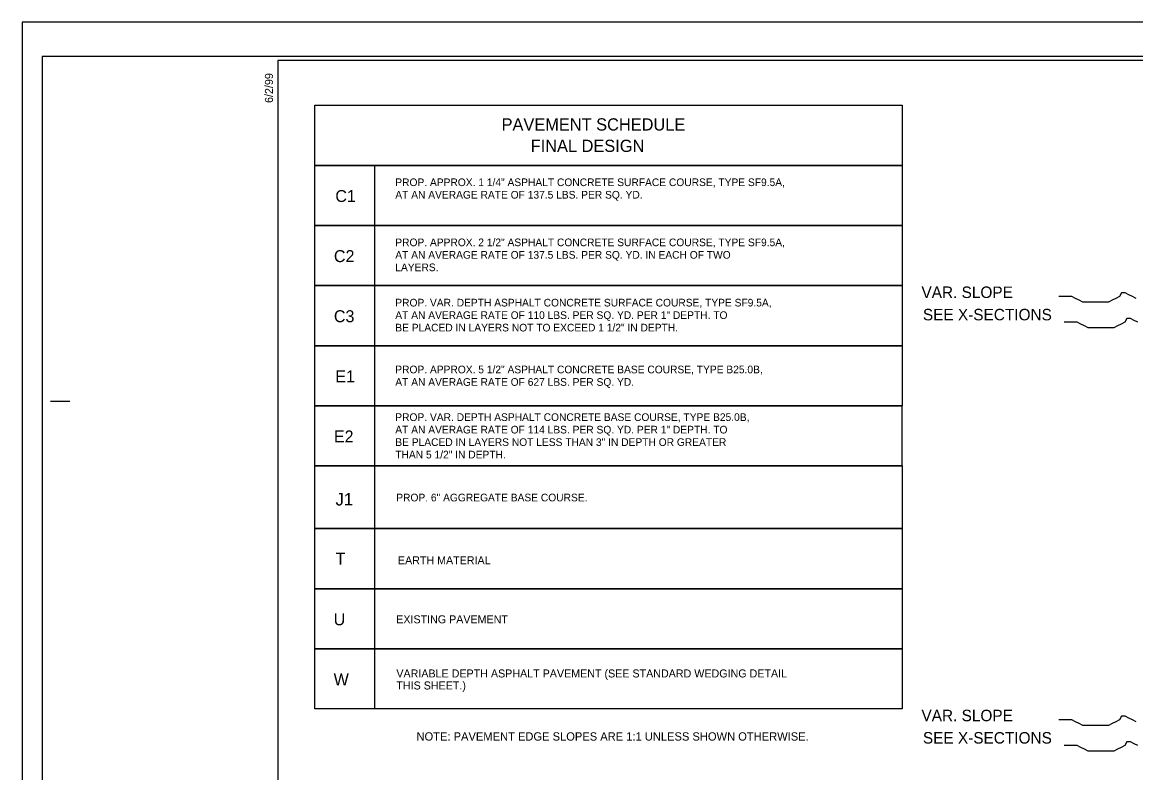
# Model space of a CAD drawing. Extents: x 573711 to 575883, y -54585 to -53485.
# Drawn here: x 573711 to 574439, y -53975 to -53485 of the extents above; entities that cross this region are included whole.
import ezdxf

# ---------------------------------------------------------------- set-up
doc = ezdxf.new("R2010")
doc.units = 0
for name, color, linetype in [('Old_Level_1', 7, 'Continuous'), ('Old_Level_19', 7, 'Continuous'), ('Old_Level_21', 7, 'Continuous'), ('Prop Pavement Schedule Description CELL', 7, 'Continuous'), ('Sheet Cutting Line CELL', 7, 'Continuous'), ('Sheet Plot Border Inside CELL', 7, 'Continuous'), ('Sheet Plot Border Outside CELL', 7, 'Continuous'), ('Sheet Typical CELL', 7, 'Continuous')]:
    doc.layers.add(name, color=color, linetype=linetype)

msp = doc.modelspace()

# ---------------------------------------------------------------- linework, layer by layer
at = {"layer": 'Old_Level_1'}
for points in [[(574439.14, -53665.45), (574436.74, -53664.26), (574434.33, -53663.05), (574431.93, -53661.84), (574429.53, -53661.84), (574428.32, -53664.26), (574425.92, -53665.45), (574423.51, -53666.66), (574421.11, -53667.86), (574418.71, -53667.86), (574416.3, -53667.86), (574413.9, -53667.86), (574411.5, -53667.86), (574409.09, -53667.86), (574406.69, -53667.86), (574404.29, -53667.86), (574401.88, -53666.66), (574399.48, -53665.46), (574397.08, -53664.26), (574393.47, -53664.26), (574391.06, -53664.26), (574388.66, -53664.26)], [(574440.25, -53681.03), (574437.84, -53679.83), (574435.44, -53678.62), (574433.04, -53678.62), (574431.83, -53681.03), (574429.43, -53682.23), (574427.02, -53683.44), (574424.62, -53684.63), (574422.22, -53684.63), (574419.81, -53684.63), (574417.41, -53684.64), (574415.01, -53684.64), (574412.61, -53684.64), (574410.2, -53684.64), (574407.8, -53684.64), (574405.4, -53683.44), (574402.99, -53682.23), (574400.59, -53681.04), (574396.98, -53681.04), (574394.58, -53681.04), (574392.17, -53681.04)], [(574439.14, -53941.97), (574436.74, -53940.78), (574434.33, -53939.57), (574431.93, -53938.37), (574429.53, -53938.37), (574428.32, -53940.78), (574425.92, -53941.98), (574423.51, -53943.18), (574421.11, -53944.38), (574418.71, -53944.38), (574416.3, -53944.38), (574413.9, -53944.38), (574411.5, -53944.38), (574409.09, -53944.38), (574406.69, -53944.38), (574404.29, -53944.38), (574401.88, -53943.18), (574399.48, -53941.98), (574397.08, -53940.78), (574393.47, -53940.78), (574391.06, -53940.78), (574388.66, -53940.78)], [(574440.25, -53957.55), (574437.84, -53956.35), (574435.44, -53955.14), (574433.04, -53955.14), (574431.83, -53957.56), (574429.43, -53958.75), (574427.02, -53959.96), (574424.62, -53961.16), (574422.22, -53961.16), (574419.81, -53961.16), (574417.41, -53961.16), (574415.01, -53961.16), (574412.61, -53961.16), (574410.2, -53961.16), (574407.8, -53961.16), (574405.4, -53959.96), (574402.99, -53958.75), (574400.59, -53957.56), (574396.98, -53957.56), (574394.58, -53957.56), (574392.17, -53957.56)]]:
    msp.add_lwpolyline(points, dxfattribs=at)
at = {"layer": 'Old_Level_19'}
for p, q in [((573902.3, -53774.89), (573902.3, -53735.62)), ((573902.3, -53735.62), (574286.3, -53735.62)), ((573941.57, -53774.89), (573941.57, -53735.62)), ((574286.3, -53774.89), (574286.3, -53735.62)), ((573941.57, -53774.89), (573902.3, -53774.89)), ((573941.57, -53774.89), (573902.3, -53774.89)), ((574286.3, -53774.89), (573941.57, -53774.89)), ((574286.3, -53774.89), (573941.57, -53774.89))]:
    msp.add_line(p, q, dxfattribs=at)
msp.add_lwpolyline([(573902.3, -53539.26), (574286.31, -53539.26), (574286.31, -53578.53), (573902.3, -53578.53)], close=True, dxfattribs=at)
for points in [[(573941.57, -53617.81), (573902.3, -53617.81), (573902.3, -53578.53), (574286.3, -53578.53), (574286.3, -53617.81), (573941.57, -53617.81), (573941.57, -53578.53)], [(573941.57, -53657.08), (573902.3, -53657.08), (573902.3, -53617.81), (574286.3, -53617.81), (574286.3, -53657.08), (573941.57, -53657.08), (573941.57, -53617.81)], [(573941.57, -53696.35), (573902.3, -53696.35), (573902.3, -53657.08), (574286.3, -53657.08), (574286.3, -53696.35), (573941.57, -53696.35), (573941.57, -53657.08)], [(573941.57, -53735.62), (573902.3, -53735.62), (573902.3, -53696.35), (574286.3, -53696.35), (574286.3, -53735.62), (573941.57, -53735.62), (573941.57, -53696.35)], [(573941.57, -53855.07), (573902.3, -53855.07), (573902.3, -53815.8), (574286.3, -53815.8), (574286.3, -53855.07), (573941.57, -53855.07), (573941.57, -53815.8)], [(573941.57, -53894.35), (573902.3, -53894.35), (573902.3, -53855.07), (574286.3, -53855.07), (574286.3, -53894.35), (573941.57, -53894.35), (573941.57, -53855.07)], [(573941.62, -53933.67), (573902.3, -53933.67), (573902.3, -53894.35), (574286.3, -53894.35), (574286.3, -53933.67), (573941.62, -53933.67), (573941.62, -53894.35)]]:
    msp.add_lwpolyline(points, dxfattribs=at)
at = {"layer": 'Prop Pavement Schedule Description CELL'}
msp.add_line((573941.62, -53933.67), (573941.62, -53933.67), dxfattribs=at)
msp.add_lwpolyline([(573941.57, -53815.8), (573902.3, -53815.8), (573902.3, -53774.89), (574286.3, -53774.89), (574286.3, -53815.8), (573941.57, -53815.8), (573941.57, -53774.89)], dxfattribs=at)
at = {"layer": 'Sheet Cutting Line CELL'}
for p, q in [((575395.13, -53485.01), (573711.13, -53485.01)), ((573711.13, -53485.01), (573711.13, -54585.01))]:
    msp.add_line(p, q, dxfattribs=at)
at = {"layer": 'Sheet Plot Border Inside CELL'}
msp.add_lwpolyline([(575390.63, -53507.46), (573724.13, -53507.46), (573724.13, -54562.56), (575390.63, -54562.56)], close=True, dxfattribs=at)
at = {"layer": 'Sheet Plot Border Outside CELL'}
msp.add_lwpolyline([(575395.13, -53485.01), (573711.13, -53485.01), (573711.13, -54585.01), (575395.13, -54585.01)], close=True, dxfattribs=at)
at = {"layer": 'Sheet Typical CELL'}
msp.add_line((573729.63, -53732.51), (573742.13, -53732.51), dxfattribs=at)
msp.add_lwpolyline([(575378.13, -53510.01), (573878.13, -53510.01), (573878.13, -54560.01), (575378.13, -54560.01)], close=True, dxfattribs=at)

# ---------------------------------------------------------------- texts
at = {"layer": 'Old_Level_1'}
for s, p in [('VAR. SLOPE', (574298.85, -53665.15)), ('SEE X-SECTIONS', (574299.79, -53679.75)), ('VAR. SLOPE', (574298.85, -53941.67)), ('SEE X-SECTIONS', (574299.79, -53956.27))]:
    msp.add_text(s, height=7.513, rotation=359.99476, dxfattribs=at).set_placement(p)
at = {"layer": 'Old_Level_21'}
for s, height, p in [('PAVEMENT SCHEDULE', 8, (574024.41, -53555.75)), ('FINAL DESIGN', 8, (574043.42, -53569.74)), ('C1', 7.84, (573915.76, -53602.45)), ('C2', 7.84, (573914.83, -53641.72)), ('C3', 7.84, (573914.82, -53680.99)), ('E1', 7.84, (573915.76, -53720.27)), ('E2', 7.84, (573914.83, -53759.54)), ('T ', 7.84, (573915.93, -53839.43)), ('EARTH MATERIAL', 5.224, (573956.67, -53839.15)), ('U ', 7.84, (573914.65, -53878.99)), ('EXISTING PAVEMENT', 5.224, (573955.57, -53877.7)), ('W ', 7.85, (573914.66, -53918.29)), ('VARIABLE DEPTH ASPHALT PAVEMENT (SEE STANDARD WEDGING DETAIL', 5.2305, (573955.64, -53913.07)), ('THIS SHEET.)', 5.2305, (573955.64, -53920.92))]:
    msp.add_text(s, height=height, dxfattribs=at).set_placement(p)
at = {"layer": 'Prop Pavement Schedule Description CELL'}
for s, height, p in [('PROP. APPROX. 1 1/4" ASPHALT CONCRETE SURFACE COURSE, TYPE SF9.5A,', 5, (573954.94, -53592.04)), ('AT AN AVERAGE RATE OF 137.5 LBS. PER SQ. YD. ', 5, (573954.94, -53600.2)), ('PROP. APPROX. 2 1/2" ASPHALT CONCRETE SURFACE COURSE, TYPE SF9.5A,', 5, (573954.94, -53631.31)), ('AT AN AVERAGE RATE OF 137.5 LBS. PER SQ. YD. IN EACH OF TWO ', 5, (573954.94, -53639.47)), ('LAYERS.', 5, (573954.94, -53647.63)), ('PROP. VAR. DEPTH ASPHALT CONCRETE SURFACE COURSE, TYPE SF9.5A,', 5, (573954.94, -53670.69)), ('AT AN AVERAGE RATE OF 110 LBS. PER SQ. YD. PER 1" DEPTH. TO', 5, (573954.94, -53678.85)), ('BE PLACED IN LAYERS NOT TO EXCEED 1 1/2" IN DEPTH.', 5, (573954.94, -53687)), ('PROP. APPROX. 5 1/2" ASPHALT CONCRETE BASE COURSE, TYPE B25.0B,', 5, (573954.94, -53714.36)), ('AT AN AVERAGE RATE OF 627 LBS. PER SQ. YD.', 5, (573954.94, -53722.52)), ('PROP. VAR. DEPTH ASPHALT CONCRETE BASE COURSE, TYPE B25.0B,', 5, (573954.94, -53745.5)), ('AT AN AVERAGE RATE OF 114 LBS. PER SQ. YD. PER 1" DEPTH. TO', 5, (573954.94, -53753.66)), ('BE PLACED IN LAYERS NOT LESS THAN 3" IN DEPTH OR GREATER', 5, (573954.94, -53761.82)), ('THAN 5 1/2" IN DEPTH.', 5, (573954.94, -53769.97)), ('J1', 8.167, (573915.88, -53800.72)), ('PROP. 6" AGGREGATE BASE COURSE.', 5, (573955.57, -53798.02)), ('NOTE: PAVEMENT EDGE SLOPES ARE 1:1 UNLESS SHOWN OTHERWISE.', 5.4417, (573968.81, -53954.33))]:
    msp.add_text(s, height=height, dxfattribs=at).set_placement(p)
at = {"layer": 'Sheet Typical CELL'}
msp.add_text('6/2/99', height=5.25, rotation=90, dxfattribs=at).set_placement((573874.98, -53537.76))

doc.saveas('drawing.dxf')
